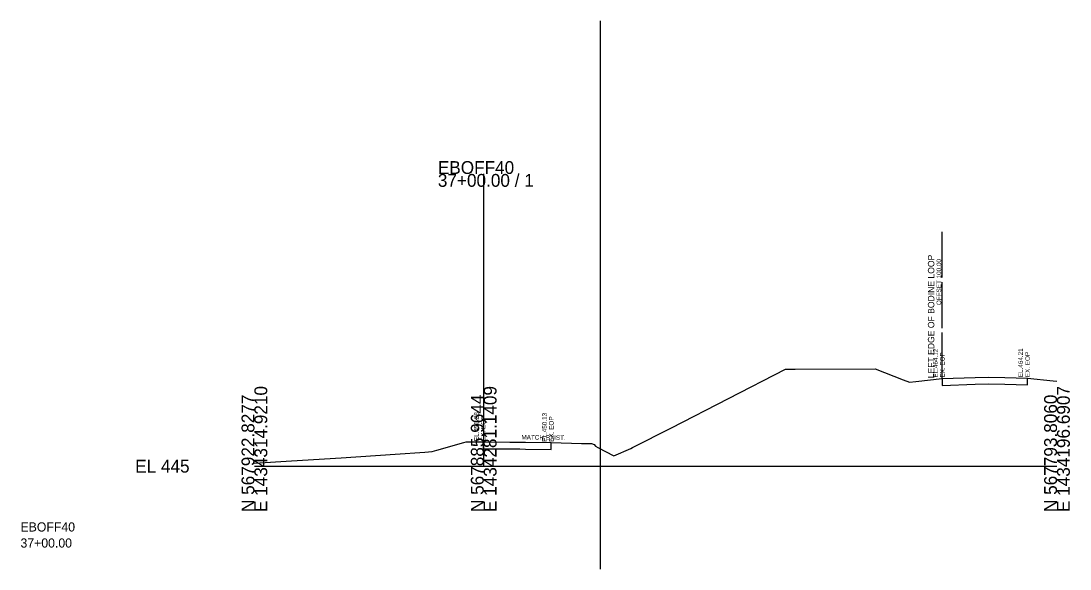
# Model space of a CAD drawing. Extents: x 1433207 to 1452258, y 558237 to 582284.
# Drawn here: x 1450882 to 1451110.7, y 565241.7 to 565361.2 of the extents above; entities that cross this region are included whole.
import ezdxf

# ---------------------------------------------------------------- set-up
doc = ezdxf.new("R2010")
doc.units = 0
for name, color, linetype in [('DESIGN - EARTHWORK - Excavation Limit Lines', 7, 'Continuous'), ('DESIGN - SHEET - Light Grid', 7, 'Continuous'), ('DESIGN - TYPICAL - Slope Tie Text', 7, 'Continuous'), ('DESIGN - TYPICAL - Warning Text', 7, 'Continuous'), ('SURVEY - GROUND - Existing Pavement Layer', 7, 'Continuous'), ('SURVEY - GROUND - Existing Pavement Text', 7, 'Continuous'), ('SURVEY - GROUND - Top of Ground', 7, 'Continuous'), ('SURVEY - PROPERTY - ROW Lines', 7, 'Continuous'), ('SURVEY - PROPERTY - ROW Lines Text', 7, 'Continuous')]:
    doc.layers.add(name, color=color, linetype=linetype)

msp = doc.modelspace()

# ---------------------------------------------------------------- linework, layer by layer
at = {"layer": 'DESIGN - EARTHWORK - Excavation Limit Lines'}
msp.add_line((1451008.3, 565361.17), (1451008.3, 565241.67), dxfattribs=at)
at = {"layer": 'DESIGN - SHEET - Light Grid'}
for p, q in [((1450982.89, 565264.09), (1450982.89, 565327.81)), ((1450932.89, 565264.09), (1450982.89, 565264.09)), ((1450982.89, 565264.09), (1451107.89, 565264.09))]:
    msp.add_line(p, q, dxfattribs=at)
at = {"layer": 'SURVEY - GROUND - Existing Pavement Layer'}
for p, q in [((1451082.89, 565283.21), (1451082.89, 565281.71)), ((1451101.46, 565281.8), (1451101.46, 565283.3)), ((1451082.89, 565281.71), (1451090.08, 565281.94)), ((1451090.08, 565281.94), (1451092.87, 565282.03)), ((1451092.87, 565282.03), (1451096.55, 565281.94)), ((1451096.55, 565281.94), (1451101.46, 565281.8)), ((1450982.78, 565269.37), (1450982.78, 565267.87)), ((1450997.63, 565267.72), (1450997.63, 565269.22)), ((1450982.78, 565267.87), (1450988.59, 565267.85)), ((1450988.59, 565267.85), (1450990.75, 565267.84)), ((1450990.75, 565267.84), (1450992.01, 565267.82)), ((1450992.01, 565267.82), (1450997.63, 565267.72))]:
    msp.add_line(p, q, dxfattribs=at)
at = {"layer": 'SURVEY - GROUND - Top of Ground'}
msp.add_lwpolyline([(1450932.89, 565264.76), (1450940.95, 565265.23), (1450951.8, 565265.93), (1450963.55, 565266.69), (1450970.06, 565267.18), (1450971.65, 565267.3), (1450972.64, 565267.58), (1450978.56, 565269.22), (1450979.06, 565269.37), (1450981.09, 565269.37), (1450982.78, 565269.37), (1450988.59, 565269.35), (1450990.75, 565269.34), (1450992.01, 565269.32), (1450997.63, 565269.22), (1451004.21, 565269.07), (1451006.37, 565269.02), (1451006.94, 565268.83), (1451007.3, 565268.43), (1451007.75, 565268.2), (1451011.3, 565266.36), (1451014.96, 565267.94), (1451015.37, 565268.13), (1451023.87, 565272.48), (1451048.66, 565285.21), (1451050.8, 565285.22), (1451068.24, 565285.33), (1451074.36, 565282.93), (1451075.76, 565282.43), (1451077.13, 565282.58), (1451082.89, 565283.21), (1451090.08, 565283.44), (1451092.87, 565283.53), (1451096.55, 565283.44), (1451101.46, 565283.3), (1451107.07, 565282.72), (1451107.89, 565282.63)], dxfattribs=at)
at = {"layer": 'SURVEY - PROPERTY - ROW Lines'}
for p, q in [((1451082.89, 565305.21), (1451082.89, 565315.21)), ((1451082.89, 565294.21), (1451082.89, 565304.21)), ((1451082.89, 565283.21), (1451082.89, 565293.21))]:
    msp.add_line(p, q, dxfattribs=at)

# ---------------------------------------------------------------- texts
at = {"layer": 'DESIGN - SHEET - Light Grid'}
for s, p in [('EBOFF40', (1450972.89, 565327.81)), ('37+00.00 / 1', (1450972.89, 565325.01)), ('EL 445', (1450906.89, 565262.69))]:
    msp.add_text(s, height=2.8, dxfattribs=at).set_placement(p)
for s, p in [('E 1434314.9210', (1450935.69, 565254.09)), ('E 1434281.1409', (1450985.69, 565254.09)), ('E 1434196.6907', (1451110.69, 565254.09)), ('N 567922.8277', (1450932.89, 565254.09)), ('N 567885.9644', (1450982.89, 565254.09)), ('N 567793.8060', (1451107.89, 565254.09))]:
    msp.add_text(s, height=2.8, rotation=90, dxfattribs=at).set_placement(p)
at = {"layer": 'DESIGN - TYPICAL - Slope Tie Text'}
msp.add_text('MATCH EXIST.', height=1, rotation=359.3609, dxfattribs=at).set_placement((1450991.11, 565269.92))
at = {"layer": 'DESIGN - TYPICAL - Warning Text'}
for s, p in [('EBOFF40', (1450881.89, 565249.84)), ('37+00.00', (1450881.89, 565246.34))]:
    msp.add_text(s, height=2, dxfattribs=at).set_placement(p)
at = {"layer": 'SURVEY - GROUND - Existing Pavement Text'}
for s, p in [('EL.464.12', (1451081.88, 565283.41)), ('EL.464.21', (1451100.45, 565283.5)), ('EX. EOP', (1451083.39, 565283.41)), ('EX. EOP', (1451101.96, 565283.5)), ('EL.450.28', (1450981.78, 565269.57)), ('EL.450.13', (1450996.63, 565269.42)), ('EX. EOP', (1450983.28, 565269.57)), ('EX. EOP', (1450998.13, 565269.42))]:
    msp.add_text(s, height=1, rotation=90, dxfattribs=at).set_placement(p)
at = {"layer": 'SURVEY - PROPERTY - ROW Lines Text'}
for s, height, p in [('LEFT EDGE OF BODINE LOOP', 1.4, (1451081.14, 565283.26)), ('OFFSET 100.00', 1, (1451082.64, 565299.21))]:
    msp.add_text(s, height=height, rotation=90, dxfattribs=at).set_placement(p)

doc.saveas('drawing.dxf')
